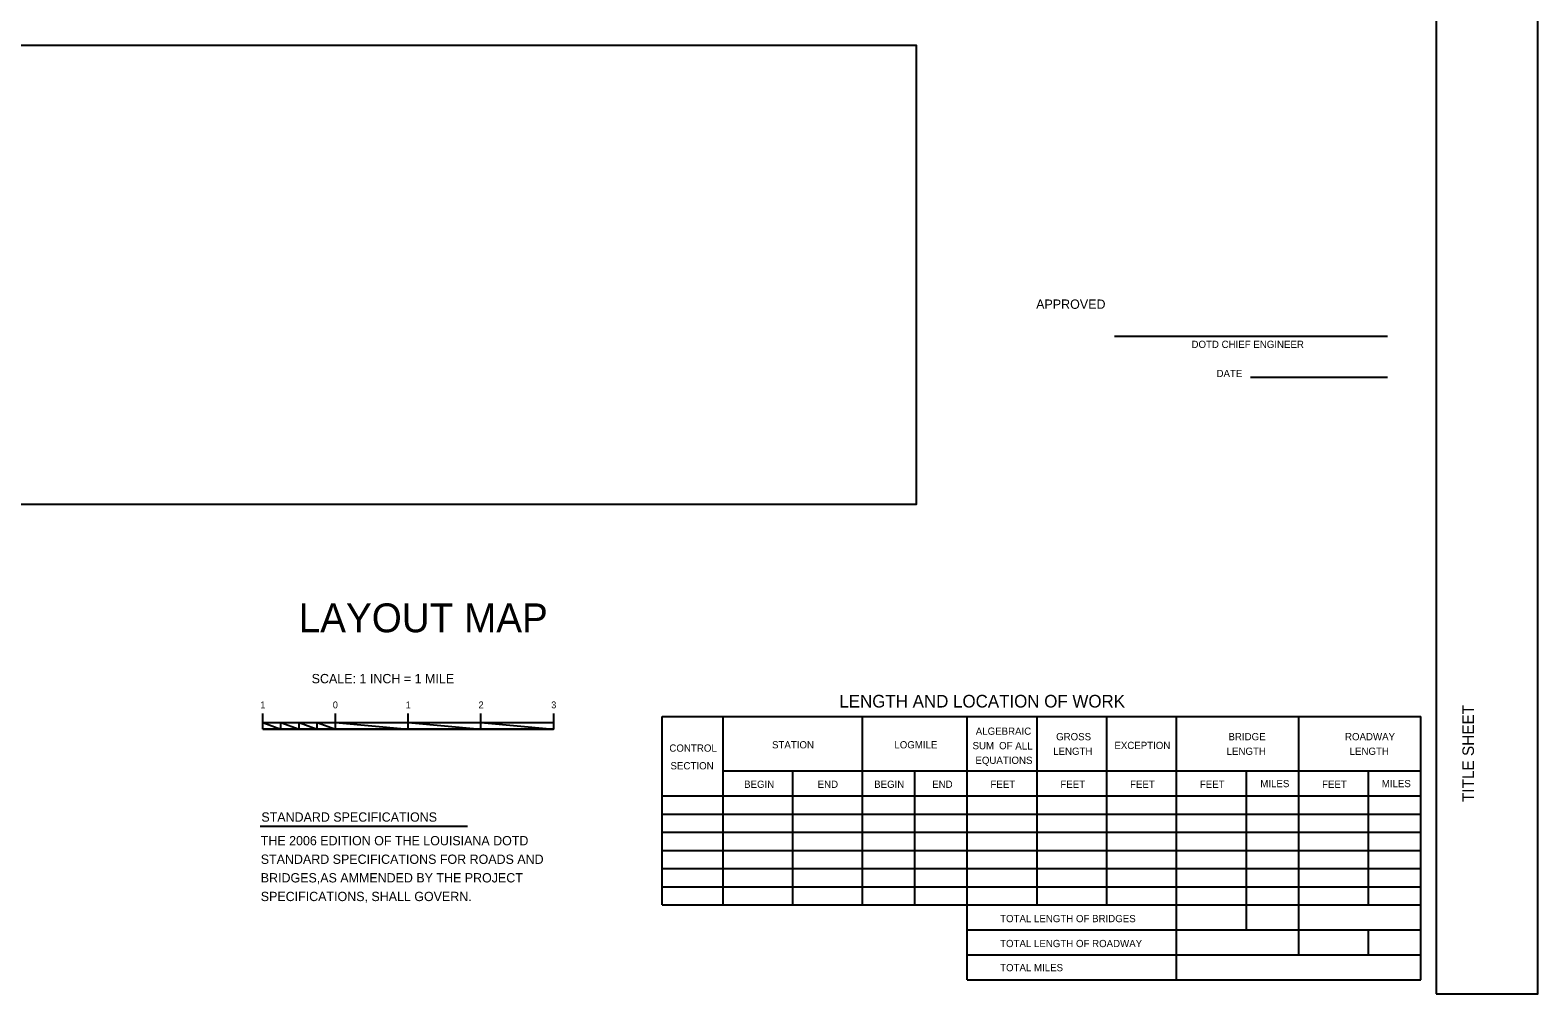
# Model space of a CAD drawing. Extents: x 0.19 to 2.82, y 0.04 to 1.79.
# Drawn here: x 1.088 to 2.817, y 0.042 to 1.147 of the extents above; entities that cross this region are included whole.
import ezdxf

# ---------------------------------------------------------------- set-up
doc = ezdxf.new("R2010")
doc.units = 0
for name, color, linetype in [('Annotation', 7, 'Continuous'), ('Layout Map Info', 7, 'Continuous'), ('Standard Info', 7, 'Continuous')]:
    doc.layers.add(name, color=color, linetype=linetype)

msp = doc.modelspace()

# ---------------------------------------------------------------- linework, layer by layer
at = {"layer": 'Annotation'}
msp.add_lwpolyline([(2.7, 0.0417), (2.8167, 0.0417), (2.8167, 1.7916), (2.7, 1.7916)], close=True, dxfattribs=at)
at = {"layer": 'Layout Map Info'}
msp.add_lwpolyline([(0.9038, 0.6035), (2.1045, 0.6035), (2.1045, 1.1298), (0.9038, 1.1298)], close=True, dxfattribs=at)
at = {"layer": 'Standard Info'}
for p, q in [((2.3314, 0.7963), (2.6442, 0.7963)), ((2.4874, 0.7493), (2.6442, 0.7493)), ((1.3548, 0.3452), (1.3548, 0.3635)), ((1.4381, 0.3452), (1.4381, 0.3635)), ((1.5215, 0.3452), (1.5215, 0.3635)), ((1.6048, 0.3452), (1.6048, 0.3635)), ((1.6881, 0.3635), (1.6881, 0.3452)), ((1.3548, 0.353), (1.6881, 0.353)), ((1.8126, 0.36), (2.6826, 0.36)), ((1.8126, 0.1438), (1.8126, 0.36)), ((1.8826, 0.1438), (1.8826, 0.36)), ((2.0426, 0.1438), (2.0426, 0.36)), ((2.1626, 0.0579), (2.1626, 0.36)), ((2.2426, 0.1438), (2.2426, 0.36)), ((2.3226, 0.1438), (2.3226, 0.36)), ((2.4026, 0.0579), (2.4026, 0.36)), ((2.5426, 0.0866), (2.5426, 0.36)), ((2.6826, 0.0579), (2.6826, 0.36)), ((1.3548, 0.3452), (1.6881, 0.3452)), ((1.8826, 0.2975), (2.6826, 0.2975)), ((1.9626, 0.1438), (1.9626, 0.2975)), ((2.1026, 0.1438), (2.1026, 0.2975)), ((2.4826, 0.1152), (2.4826, 0.2975)), ((2.6226, 0.1438), (2.6226, 0.2975)), ((1.8126, 0.2688), (2.6826, 0.2688)), ((1.8126, 0.248), (2.6826, 0.248)), ((1.3519, 0.2341), (1.5897, 0.2341)), ((1.8126, 0.2271), (2.6826, 0.2271)), ((1.8126, 0.2063), (2.6826, 0.2063)), ((1.8126, 0.1855), (2.6826, 0.1855)), ((1.8126, 0.1646), (2.6826, 0.1646)), ((1.8126, 0.1438), (2.6826, 0.1438)), ((2.1626, 0.1152), (2.6826, 0.1152)), ((2.6226, 0.0866), (2.6226, 0.1152)), ((2.1626, 0.0866), (2.6826, 0.0866)), ((2.1626, 0.0579), (2.6826, 0.0579))]:
    msp.add_line(p, q, dxfattribs=at)
for points in [[(1.3548, 0.3452), (1.3548, 0.353), (1.3755, 0.3452)], [(1.3756, 0.3452), (1.3756, 0.353), (1.3965, 0.3452)], [(1.3966, 0.3452), (1.3966, 0.353), (1.4174, 0.3452)], [(1.4173, 0.3452), (1.4173, 0.353), (1.4381, 0.3452)], [(1.4381, 0.3452), (1.4381, 0.353), (1.5215, 0.3452)], [(1.5215, 0.3452), (1.5215, 0.353), (1.6048, 0.3452)], [(1.6048, 0.3452), (1.6048, 0.353), (1.6881, 0.3452)]]:
    msp.add_lwpolyline(points, close=True, dxfattribs=at)

# ---------------------------------------------------------------- texts
at = {"layer": 'Annotation'}
msp.add_text('           TITLE SHEET           ', height=0.013166, rotation=90, dxfattribs=at).set_placement((2.7434, 0.2079))
at = {"layer": 'Standard Info'}
for s, height, p in [('APPROVED', 0.0107, (2.2415, 0.8276)), ('DOTD CHIEF ENGINEER', 0.0083, (2.4196, 0.7827)), ('DATE', 0.0083, (2.4483, 0.7493)), ('LAYOUT MAP', 0.03313, (1.3961, 0.4565)), ('SCALE: 1 INCH = 1 MILE', 0.0107, (1.4109, 0.398)), ('LENGTH AND LOCATION OF WORK', 0.0145, (2.0159, 0.3702)), ('1', 0.0078, (1.3521, 0.3693)), ('0', 0.0078, (1.4352, 0.3693)), ('1', 0.0078, (1.5187, 0.3693)), ('2', 0.0078, (1.6023, 0.3693)), ('3', 0.0078, (1.6856, 0.3693)), ('ALGEBRAIC', 0.0083, (2.1723, 0.3389)), ('STATION', 0.0083, (1.9387, 0.3233)), ('LOGMILE', 0.0083, (2.079, 0.3233)), ('SUM', 0.0083, (2.1686, 0.3223)), ('OF', 0.00833, (2.199, 0.3223)), ('ALL', 0.00833, (2.2176, 0.322)), ('GROSS', 0.0083, (2.2644, 0.3326)), ('EXCEPTION', 0.0083, (2.3312, 0.3226)), ('BRIDGE', 0.0083, (2.462, 0.3326)), ('ROADWAY', 0.0083, (2.5956, 0.3326)), ('CONTROL', 0.00833, (1.821, 0.3195)), ('EQUATIONS', 0.0083, (2.1719, 0.3055)), ('LENGTH', 0.0083, (2.261, 0.3159)), ('LENGTH', 0.0083, (2.4599, 0.3159)), ('LENGTH', 0.0083, (2.6009, 0.3159)), ('SECTION', 0.00833, (1.8223, 0.2992)), ('BEGIN', 0.0083, (1.9067, 0.278)), ('END', 0.0083, (1.991, 0.278)), ('BEGIN', 0.0083, (2.0558, 0.278)), ('END', 0.0083, (2.1223, 0.278)), ('FEET', 0.0083, (2.1891, 0.278)), ('FEET', 0.0083, (2.2693, 0.278)), ('FEET', 0.0083, (2.3492, 0.278)), ('FEET', 0.0083, (2.4292, 0.278)), ('MILES', 0.0083, (2.4985, 0.2788)), ('FEET', 0.0083, (2.5693, 0.278)), ('MILES', 0.0083, (2.6377, 0.2788)), ('STANDARD SPECIFICATIONS', 0.01067, (1.3533, 0.2392)), ('THE 2006 EDITION OF THE LOUISIANA DOTD ', 0.01067, (1.3526, 0.2121)), ('STANDARD SPECIFICATIONS FOR ROADS AND ', 0.01067, (1.3526, 0.1908)), ('BRIDGES,AS AMMENDED BY THE PROJECT ', 0.01067, (1.3526, 0.1695)), ('SPECIFICATIONS, SHALL GOVERN. ', 0.01067, (1.3526, 0.1481)), ('TOTAL LENGTH OF BRIDGES', 0.0083, (2.2002, 0.1239)), ('TOTAL LENGTH OF ROADWAY', 0.0083, (2.2002, 0.0953)), ('TOTAL MILES', 0.0083, (2.2002, 0.0676))]:
    msp.add_text(s, height=height, dxfattribs=at).set_placement(p)

doc.saveas('drawing.dxf')
